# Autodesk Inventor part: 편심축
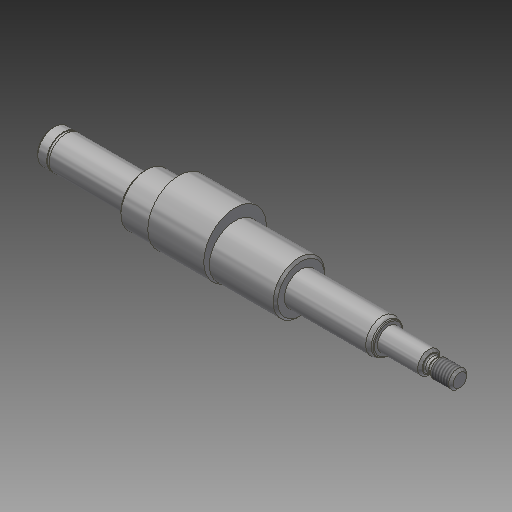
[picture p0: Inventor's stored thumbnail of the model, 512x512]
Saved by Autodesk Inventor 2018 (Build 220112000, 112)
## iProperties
Created: 2015-09
Part Number: 편심축
Material: 강철, 연강
Document SubType Name: Modeling
Designer: mduedu
Density: 1 g/cm^3
Appearance: 강철
Author: mduedu
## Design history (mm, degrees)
sketch "스케치1"
  geometry: L1 (-91, 0)-(91, 0); L2 (-91, 0)-(-91, 7.5); L3 (-91, 7.5)-(-49.85, 7.5); L4 (-49.85, 7.5)-(-49.85, 11.5); L5 (-49.85, 11.5)-(20.15, 11.5); L6 (20.15, 11.5)-(20.15, 7.5); L7 (20.15, 7.5)-(59.15, 7.5); L8 (59.15, 7.5)-(59.15, 5); L9 (59.15, 5)-(78.15, 5); L10 (78.15, 5)-(78.15, 3); L11 (78.15, 3)-(80.15, 3); L12 (81.882, 4)-(91, 4); L13 (91, 4)-(91, 0); L14 (80.15, 3)-(81.882, 4); 2 further points
  constraints: 28 end point, 9 parallel, 2 perpendicular, 1 coincident, 1 collinear, 1 horizontal, 1 midpoint
  dimensions: "d0" = 41.15 distance of L2.end L3.end; "d2" = 70 distance of L4.end L5.end; "d3" = 39 distance of L6.end L7.end; "d4" = 182 distance of L1.start L1.end; "d5" = 19 distance of L8.end L9.end; "d7" = 8 diameter of L12 L1; "d8" = 6 diameter of L11 L1; "d9" = 10 diameter of L9 L1; "d10" = 15 diameter of L7 L1; "d11" = 23 diameter of L5 L1; "d12" = 15 diameter of L3 L1; "d40" = 30 deg angle of L14 L12; "d41" = 2 distance of L10.end L11.end; "d42" = 3.73205 horizontal distance of L12.start L10.end (derived)
revolve "회전1" sketch "스케치1" stored, may be unused: angle "d13" = 90 deg
fillet "모깎기1" dims "d43" = 0.6
sketch "스케치2"
  geometry: L1 (-91, 7.5)-(-49.85, 7.5) reference; L2 (-91, -7.5)-(-91, 7.5) reference; L3 (91, -4)-(91, 4) reference; L4 (-91, 0)-(91, 0); L5 (-86, 7.5)-(-84.85, 7.5); L6 (-84.85, 7.5)-(-84.85, 7.15); L7 (-84.85, 7.15)-(-86, 7.15); L8 (-86, 7.15)-(-86, 7.5); 1 further point
  constraints: 10 end point, 2 midpoint, 2 parallel, 1 horizontal, 1 perpendicular, 1 point on line
  dimensions: "d14" = 5 distance between parallel lines of L8 L2; "d15" = 14.3 diameter of L7 L4; "d16" = 1.15 distance of L6.end L7.end
revolve "회전2" sketch "스케치2" stored, may be unused: angle "d17" = 90 deg
node "작업 평면1"
sketch "스케치3"
  geometry: C1 r 11.5 at (0, 0) reference; C2 r 14 at (0, 2.5); 1 further point
  constraints: 1 centre point, 1 tangent, 1 vertical alignment
  dimensions: "d19" = 28 diameter of C2
extrude "돌출1" join sketch "스케치3" distance "d21" = 25; taper "d22" = 0 deg
node "작업 평면2"
sketch "스케치4"
  geometry: L1 (9.5, 7.5)-(9.5, -7.5) reference; L2 (-9.5, 5)-(-9.5, -5) reference; L3 (9.5, 0)-(-9.5, 0); L4 (-5, -1.5)-(4, -1.5); L5 (4, 1.5)-(-5, 1.5); A1 r 1.5 centre (4, 0) between (4, -1.5) and (4, 1.5); A2 r 1.5 centre (-5, 0) between (-5, 1.5) and (-5, -1.5); 1 further point
  constraints: 6 end point, 4 point on circle, 4 tangent, 2 centre point, 2 midpoint, 2 parallel, 1 point on line
  dimensions: "d23" = 3 distance between parallel lines of L5 L4; "d25" = 12 dimension on A2 A1; "d26" = 3 distance edge to line of A2 L2
extrude "돌출2" cut sketch "스케치4" distance "d27" = 1.8; taper "d28" = 0 deg
chamfer "모따기1" distance "d29" = 1; stored, may be unused: second distance "d30" = 2, angle "d31" = 45 deg
sketch "스케치5"
  geometry: L1 (80.289, 3.08)-(81.882, 4) reference; L2 (81.882, 4)-(91, 4) reference; L3 (91, 4)-(91, -4) reference; L4 (91, -4)-(81.882, -4) reference; L5 (81.882, -4)-(80.289, -3.08) reference; L6 (79.989, -3)-(78.75, -3) reference; L7 (78.15, -3.6)-(78.15, -5) reference; L8 (78.15, -5)-(75.15, -5) reference; L9 (75.15, -5)-(75.15, -3.2) reference; L10 (75.15, -3.2)-(63.15, -3.2) reference; L11 (63.15, -3.2)-(63.15, -5) reference; L12 (63.15, -5)-(59.15, -5) reference; L13 (59.15, -5)-(59.15, -7.5) reference; L14 (59.15, -7.5)-(20.15, -7.5) reference; L15 (20.15, -7.5)-(20.15, -10.5) reference; L16 (20.15, -10.5)-(19.15, -11.5) reference; L17 (19.15, -11.5)-(-9.35, -11.5) reference; L18 (-9.35, -11.5)-(-34.35, -11.5) reference; L19 (-34.35, -11.5)-(-48.85, -11.5) reference; L20 (-48.85, -11.5)-(-49.85, -10.5) reference; L21 (-49.85, -10.5)-(-49.85, -7.5) reference; L22 (-49.85, -7.5)-(-84.85, -7.5) reference; L23 (-84.85, -7.5)-(-84.85, -7.15) reference; L24 (-84.85, -7.15)-(-86, -7.15) reference; L25 (-86, -7.15)-(-86, -7.5) reference; L26 (-86, -7.5)-(-90, -7.5) reference; L27 (-90, -7.5)-(-91, -6.5) reference; L28 (-91, -6.5)-(-91, 6.5) reference; L29 (-91, 6.5)-(-90, 7.5) reference; L30 (-90, 7.5)-(-86, 7.5) reference; L31 (-86, 7.5)-(-86, 7.15) reference; L32 (-86, 7.15)-(-84.85, 7.15) reference; L33 (-84.85, 7.15)-(-84.85, 7.5) reference; L34 (-84.85, 7.5)-(-49.85, 7.5) reference; L35 (-49.85, 7.5)-(-49.85, 10.5) reference; L36 (-49.85, 10.5)-(-48.85, 11.5) reference; L37 (-48.85, 11.5)-(-34.35, 11.5) reference; L38 (-34.35, 11.5)-(-34.35, 16.5) reference; L39 (-34.35, 16.5)-(-9.35, 16.5) reference; L40 (-9.35, 16.5)-(-9.35, 11.5) reference; L41 (-9.35, 11.5)-(19.15, 11.5) reference; L42 (19.15, 11.5)-(20.15, 10.5) reference; L43 (20.15, 10.5)-(20.15, 7.5) reference; L44 (20.15, 7.5)-(59.15, 7.5) reference; L45 (59.15, 7.5)-(59.15, 5) reference; L46 (59.15, 5)-(78.15, 5) reference; L47 (78.15, 5)-(78.15, 3.6) reference; L48 (78.75, 3)-(79.989, 3) reference; L49 (0, 0)-(91, 0); L50 (59.15, -6.55)-(57.505, -7.5); L51 (57.505, -7.5)-(59.15, -7.5); L52 (59.15, -7.5)-(59.15, -6.55); A1 r 0.6 centre (79.989, 3.6) between (79.989, 3) and (80.289, 3.08) reference; A2 r 0.6 centre (79.989, -3.6) between (80.289, -3.08) and (79.989, -3) reference; A3 r 0.6 centre (78.75, -3.6) between (78.75, -3) and (78.15, -3.6) reference; A4 r 0.6 centre (78.75, 3.6) between (78.15, 3.6) and (78.75, 3) reference
  constraints: 8 end point, 2 point on line, 1 midpoint, 1 parallel, 1 perpendicular
  dimensions: "d44" = 30 deg angle of L50 L51; "d45" = 13.1 diameter of L50.start L49
revolve "회전3" sketch "스케치5" stored, may be unused: angle "d46" = 90 deg
fillet "모깎기2" dims "d47" = 4, "d48" = 0.5
feature "스레드1" dims "d32" = 10, "d33" = 0
chamfer "모따기2" distance "d34" = 1; stored, may be unused: second distance "d35" = 2, angle "d36" = 45 deg
chamfer "모따기3" distance "d37" = 1; stored, may be unused: second distance "d38" = 2, angle "d39" = 45 deg
node "솔리드1"
node "절단 모서리 투영1"
other parameters: "d18" = -29.5
